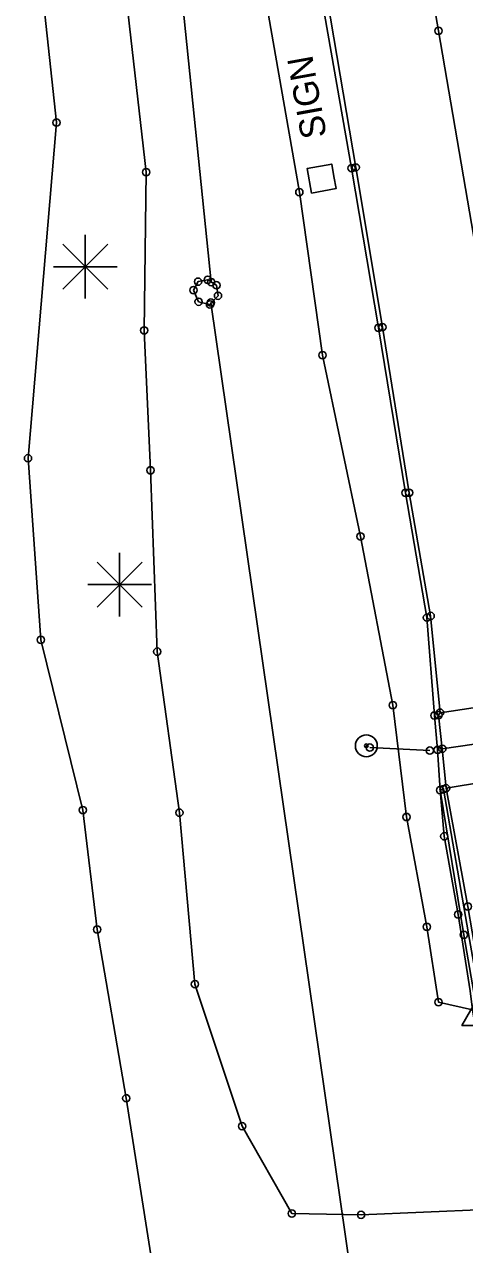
# Model space of a CAD drawing. Extents: x 21481721 to 21494985, y 8063982 to 8084842.
# Drawn here: x 21487998.5 to 21488058.9, y 8075357 to 8075524.3 of the extents above; entities that cross this region are included whole.
import ezdxf

# ---------------------------------------------------------------- set-up
doc = ezdxf.new("R2010")
doc.units = 0
for name, color, linetype in [('Drainage', 7, 'Continuous'), ('EXT_BL', 7, 'Continuous'), ('EXT_CON', 7, 'Continuous'), ('EXT_CU', 7, 'Continuous'), ('EXT_EP', 7, 'Continuous'), ('EXT_GU', 7, 'Continuous'), ('Roadways', 7, 'Continuous'), ('SurControl', 7, 'Continuous'), ('SurDrainage', 7, 'Continuous'), ('SurNaturalCells', 7, 'Continuous'), ('SurPointsNonDTM', 7, 'Continuous'), ('SurRoadPoints', 7, 'Continuous'), ('SurSurveyPoints', 7, 'Continuous')]:
    doc.layers.add(name, color=color, linetype=linetype)

msp = doc.modelspace()

# ---------------------------------------------------------------- linework, layer by layer
at = {"layer": 'Drainage'}
for points in [[(21487999.88, 8075725.11), (21488024.11, 8075488.97)], [(21488024.05, 8075486.18), (21488043.94, 8075348.32)], [(21488054.1, 8075424.75), (21488045.86, 8075425.16)]]:
    msp.add_lwpolyline(points, dxfattribs=at)
at = {"layer": 'EXT_BL'}
for points in [[(21488078.47, 8075383.41), (21488075.34, 8075404.11), (21488072.38, 8075422.27), (21488071.48, 8075427.29), (21488070.62, 8075432.22), (21488065.88, 8075460.89), (21488060.66, 8075491.95), (21488055.28, 8075523.45), (21488049.96, 8075553.99), (21488045.13, 8075582.91), (21488040.13, 8075611.89), (21488034.92, 8075642.89)], [(21488001.98, 8075638.33), (21488003.4, 8075630.75), (21488005.67, 8075621.9), (21488010.36, 8075616.83), (21488017, 8075610.19), (21488020.09, 8075597.51), (21488023.57, 8075574.98), (21488028.19, 8075550.29), (21488031.96, 8075525.57), (21488036.19, 8075501.31), (21488039.36, 8075478.97), (21488044.58, 8075454.12), (21488049.02, 8075430.98), (21488050.89, 8075415.65), (21488053.68, 8075400.59), (21488055.28, 8075390.26), (21488059.94, 8075389.21)], [(21488017.28, 8075334.44), (21488016.02, 8075354.14), (21488012.44, 8075377.08), (21488008.44, 8075400.23), (21488006.48, 8075416.6), (21488000.73, 8075439.94), (21487998.96, 8075464.83), (21488002.87, 8075510.86), (21487999.99, 8075537.67), (21487999.81, 8075563.8), (21487999.31, 8075591.97), (21488000.4, 8075622.59)], [(21488012.49, 8075527.74), (21488015.17, 8075504.07), (21488014.9, 8075482.37), (21488015.76, 8075463.18), (21488016.7, 8075438.32), (21488019.73, 8075416.24), (21488021.87, 8075392.73), (21488028.33, 8075373.25), (21488035.17, 8075361.28), (21488044.66, 8075361.1), (21488061.8, 8075361.83), (21488076.5, 8075363.75), (21488093.24, 8075366.07), (21488108.43, 8075366.94), (21488125.06, 8075367.97), (21488133.21, 8075369.83), (21488137.78, 8075363.64), (21488150.64, 8075363.06), (21488165.1, 8075362.99), (21488178.82, 8075367.47)], [(21488055.5, 8075419.32), (21488056.08, 8075413), (21488057.99, 8075402.29), (21488059.62, 8075391.81), (21488059.94, 8075389.21), (21488060.61, 8075385.21), (21488061.6, 8075379.64), (21488081.48, 8075380.83), (21488091.63, 8075381.12), (21488102.77, 8075381.78), (21488114.89, 8075382.09), (21488128.96, 8075382.93)]]:
    msp.add_lwpolyline(points, dxfattribs=at)
msp.add_lwpolyline([(21488021.66, 8075487.89), (21488022.37, 8075486.3), (21488023.93, 8075485.92), (21488025.03, 8075487.12), (21488024.82, 8075488.55), (21488023.62, 8075489.31), (21488022.29, 8075489.05)], close=True, dxfattribs=at)
at = {"layer": 'EXT_CON'}
for points in [[(21488055.5, 8075429.95), (21488070.62, 8075432.22), (21488082.68, 8075434.22), (21488094.63, 8075436.26), (21488108.51, 8075438.34)], [(21488056.32, 8075419.59), (21488072.38, 8075422.27), (21488084.32, 8075424.42), (21488096.27, 8075426.26), (21488110.61, 8075428.6)]]:
    msp.add_lwpolyline(points, dxfattribs=at)
msp.add_lwpolyline([(21488060.56, 8075389.22), (21488061.21, 8075389.27), (21488059.42, 8075399.63), (21488055.97, 8075419.46), (21488055.5, 8075419.32), (21488058.78, 8075399.49)], close=True, dxfattribs=at)
at = {"layer": 'EXT_CU'}
msp.add_lwpolyline([(21488055.5, 8075419.32), (21488055.16, 8075424.86), (21488054.72, 8075429.57), (21488053.7, 8075442.99), (21488050.75, 8075460.09), (21488047.06, 8075482.72), (21488043.36, 8075504.61), (21488039.33, 8075527.55), (21488035.55, 8075551.49), (21488031.22, 8075576.87), (21488026.72, 8075602.34), (21488022.88, 8075626.39), (21488020.38, 8075641.13)], dxfattribs=at)
at = {"layer": 'EXT_EP'}
msp.add_lwpolyline([(21488056.32, 8075419.59), (21488059.31, 8075403.38), (21488061.71, 8075389.47), (21488062.76, 8075383.11)], dxfattribs=at)
at = {"layer": 'EXT_GU'}
msp.add_lwpolyline([(21488056.32, 8075419.59), (21488055.81, 8075425.01), (21488055.29, 8075429.62), (21488055.5, 8075429.95), (21488054.21, 8075443.21), (21488051.26, 8075460.11), (21488047.59, 8075482.82), (21488043.93, 8075504.72), (21488040.05, 8075527.58), (21488036.13, 8075551.46), (21488031.81, 8075576.92), (21488027.53, 8075602.39), (21488023.43, 8075626.45), (21488020.99, 8075641.23)], dxfattribs=at)
at = {"layer": 'Roadways'}
msp.add_lwpolyline([(21488055.81, 8075425.01), (21488071.48, 8075427.29), (21488083.54, 8075429.23), (21488095.42, 8075431.16), (21488109.29, 8075433.53)], dxfattribs=at)
at = {"layer": 'SurControl'}
msp.add_lwpolyline([(21488061.04, 8075391.49), (21488063.58, 8075387.08), (21488058.49, 8075387.08)], close=True, dxfattribs=at)
at = {"layer": 'SurDrainage'}
for radius in [1.5, 0.25]:
    msp.add_circle((21488045.38, 8075425.41), radius, dxfattribs=at)
at = {"layer": 'SurNaturalCells'}
for p, q in [((21488006.81, 8075486.72), (21488006.81, 8075495.47)), ((21488003.72, 8075488), (21488009.9, 8075494.19)), ((21488009.9, 8075488), (21488003.72, 8075494.19)), ((21488002.44, 8075491.09), (21488011.18, 8075491.09)), ((21488006.81, 8075491.09), (21488006.81, 8075491.09)), ((21488011.52, 8075443.14), (21488011.52, 8075451.88)), ((21488008.43, 8075444.42), (21488014.61, 8075450.6)), ((21488014.61, 8075444.42), (21488008.43, 8075450.6)), ((21488007.15, 8075447.51), (21488015.89, 8075447.51)), ((21488011.52, 8075447.51), (21488011.52, 8075447.51))]:
    msp.add_line(p, q, dxfattribs=at)
at = {"layer": 'SurPointsNonDTM'}
for centre in [(21488024.11, 8075488.97), (21488024.05, 8075486.18), (21488045.86, 8075425.16), (21488054.1, 8075424.75)]:
    msp.add_circle(centre, 0.5, dxfattribs=at)
at = {"layer": 'SurRoadPoints'}
msp.add_lwpolyline([(21488040.93, 8075503.49), (21488040.93, 8075503.49), (21488040.63, 8075505.17), (21488037.26, 8075504.56), (21488037.87, 8075501.19), (21488041.24, 8075501.8), (21488040.93, 8075503.49)], dxfattribs=at)
at = {"layer": 'SurSurveyPoints'}
for centre in [(21488055.28, 8075523.45), (21488002.87, 8075510.86), (21488015.17, 8075504.07), (21488043.36, 8075504.61), (21488043.93, 8075504.72), (21488036.19, 8075501.31), (21488022.29, 8075489.05), (21488023.62, 8075489.31), (21488024.82, 8075488.55), (21488021.66, 8075487.89), (21488021.66, 8075487.89), (21488025.03, 8075487.12), (21488022.37, 8075486.3), (21488023.93, 8075485.92), (21488014.9, 8075482.37), (21488047.06, 8075482.72), (21488047.59, 8075482.82), (21488039.36, 8075478.97), (21487998.96, 8075464.83), (21488015.76, 8075463.18), (21488050.75, 8075460.09), (21488051.26, 8075460.11), (21488044.58, 8075454.12), (21488053.7, 8075442.99), (21488054.21, 8075443.21), (21488000.73, 8075439.94), (21488016.7, 8075438.32), (21488049.02, 8075430.98), (21488054.72, 8075429.57), (21488055.29, 8075429.62), (21488055.5, 8075429.95), (21488055.16, 8075424.86), (21488055.81, 8075425.01), (21488055.97, 8075419.46), (21488056.32, 8075419.59), (21488056.32, 8075419.59), (21488055.5, 8075419.32), (21488055.5, 8075419.32), (21488055.5, 8075419.32), (21488006.48, 8075416.6), (21488019.73, 8075416.24), (21488050.89, 8075415.65), (21488056.08, 8075413), (21488059.31, 8075403.38), (21488057.99, 8075402.29), (21488008.44, 8075400.23), (21488053.68, 8075400.59), (21488058.78, 8075399.49), (21488021.87, 8075392.73), (21488055.28, 8075390.26), (21488012.44, 8075377.08), (21488028.33, 8075373.25), (21488035.17, 8075361.28), (21488044.66, 8075361.1)]:
    msp.add_circle(centre, 0.5, dxfattribs=at)

# ---------------------------------------------------------------- texts
at = {"layer": 'SurRoadPoints'}
msp.add_text('SIGN', height=3.498, rotation=100.2617, dxfattribs=at).set_placement((21488039.97, 8075509.01))

doc.saveas('drawing.dxf')
